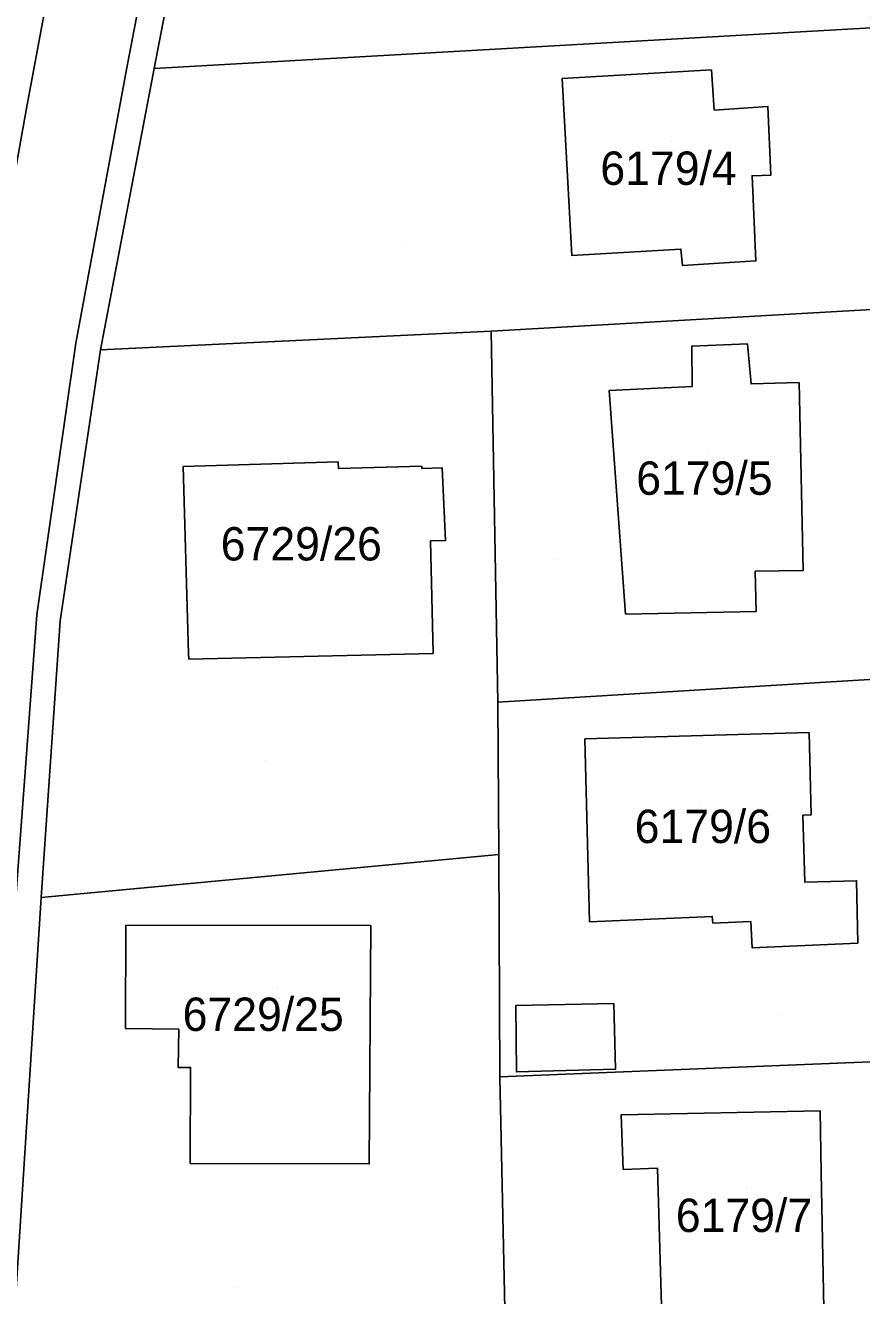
# Model space of a CAD drawing. Extents: x -266199 to -261993, y -1239047 to -1235108.
# Drawn here: x -264003.4 to -263953.2, y -1236187 to -1236110.8 of the extents above; entities that cross this region are included whole.
import ezdxf

# ---------------------------------------------------------------- set-up
doc = ezdxf.new("R2010")
doc.units = 0
for name, color, linetype in [('body_kn', 7, 'Continuous'), ('kladpar_druhypozemkov', 7, 'Continuous'), ('kladpar_hranice', 7, 'Continuous'), ('kladpar_parcelnecisla', 7, 'Continuous'), ('kladpar_plochy', 7, 'Continuous'), ('zappar_hrandruhpozemk', 7, 'Continuous')]:
    doc.layers.add(name, color=color, linetype=linetype)

msp = doc.modelspace()

# ---------------------------------------------------------------- linework, layer by layer
at = {"layer": 'body_kn'}
for p, q in [((-263997.29, -1236113.11), (-263997.29, -1236113.11)), ((-263995.69, -1236113.37), (-263995.69, -1236113.37)), ((-263971.21, -1236113.95), (-263971.21, -1236113.95)), ((-263962.26, -1236113.45), (-263962.26, -1236113.45)), ((-263958.87, -1236115.63), (-263958.87, -1236115.63)), ((-264003.37, -1236115.85), (-264003.37, -1236115.85)), ((-263962.09, -1236115.86), (-263962.09, -1236115.86)), ((-263962.09, -1236115.86), (-263962.09, -1236115.86)), ((-263959.82, -1236119.79), (-263959.82, -1236119.79)), ((-263958.7, -1236119.76), (-263958.7, -1236119.76)), ((-263970.63, -1236124.58), (-263970.63, -1236124.58)), ((-263964.09, -1236124.19), (-263964.09, -1236124.19)), ((-263964, -1236125.18), (-263964, -1236125.18)), ((-263959.59, -1236124.9), (-263959.59, -1236124.9)), ((-263975.47, -1236129.12), (-263975.47, -1236129.12)), ((-264000.38, -1236129.83), (-264000.38, -1236129.83)), ((-263963.44, -1236130.01), (-263963.44, -1236130.01)), ((-263960.1, -1236129.87), (-263960.1, -1236129.87)), ((-263998.9, -1236130.23), (-263998.9, -1236130.23)), ((-263963.42, -1236132.44), (-263963.42, -1236132.44)), ((-263959.88, -1236132.28), (-263959.88, -1236132.28)), ((-263957, -1236132.2), (-263957, -1236132.2)), ((-263957, -1236132.2), (-263957, -1236132.2)), ((-263968.39, -1236132.67), (-263968.39, -1236132.67)), ((-263984.65, -1236136.96), (-263984.65, -1236136.96)), ((-263984.65, -1236136.96), (-263984.65, -1236136.96)), ((-263993.96, -1236137.24), (-263993.96, -1236137.24)), ((-263984.64, -1236137.36), (-263984.64, -1236137.36)), ((-263979.64, -1236137.22), (-263979.64, -1236137.22)), ((-263979.64, -1236137.35), (-263979.64, -1236137.35)), ((-263978.42, -1236137.32), (-263978.42, -1236137.32)), ((-263979.11, -1236141.7), (-263979.11, -1236141.7)), ((-263978.21, -1236141.68), (-263978.21, -1236141.68)), ((-263959.63, -1236143.52), (-263959.63, -1236143.52)), ((-263956.75, -1236143.47), (-263956.75, -1236143.47)), ((-264002.72, -1236146.14), (-264002.72, -1236146.14)), ((-263967.42, -1236146.1), (-263967.42, -1236146.1)), ((-263959.58, -1236145.93), (-263959.58, -1236145.93)), ((-264001.32, -1236146.49), (-264001.32, -1236146.49)), ((-263993.63, -1236148.45), (-263993.63, -1236148.45)), ((-263978.96, -1236148.45), (-263978.96, -1236148.45)), ((-263993.62, -1236148.79), (-263993.62, -1236148.79)), ((-263975.07, -1236151.37), (-263975.07, -1236151.37)), ((-263969.85, -1236153.57), (-263969.85, -1236153.57)), ((-263956.4, -1236153.19), (-263956.4, -1236153.19)), ((-263956.77, -1236158.14), (-263956.77, -1236158.14)), ((-263956.27, -1236158.12), (-263956.27, -1236158.12)), ((-263975.01, -1236160.51), (-263975.01, -1236160.51)), ((-263975.01, -1236160.51), (-263975.01, -1236160.51)), ((-263956.66, -1236162.16), (-263956.66, -1236162.16)), ((-263953.55, -1236162.08), (-263953.55, -1236162.08)), ((-264002.46, -1236163.09), (-264002.46, -1236163.09)), ((-264002.46, -1236163.09), (-264002.46, -1236163.09)), ((-263962.21, -1236164.22), (-263962.21, -1236164.22)), ((-263997.39, -1236164.75), (-263997.39, -1236164.75)), ((-263982.69, -1236164.77), (-263982.69, -1236164.77)), ((-263969.57, -1236164.54), (-263969.57, -1236164.54)), ((-263962.17, -1236164.62), (-263962.17, -1236164.62)), ((-263962.17, -1236164.62), (-263962.17, -1236164.62)), ((-263959.89, -1236164.53), (-263959.89, -1236164.53)), ((-263953.48, -1236165.82), (-263953.48, -1236165.82)), ((-263959.82, -1236166.1), (-263959.82, -1236166.1)), ((-263974, -1236169.56), (-263974, -1236169.56)), ((-263968.12, -1236169.44), (-263968.12, -1236169.44)), ((-263968.12, -1236169.44), (-263968.12, -1236169.44)), ((-263997.4, -1236170.95), (-263997.4, -1236170.95)), ((-263994.22, -1236170.99), (-263994.22, -1236170.99)), ((-263994.26, -1236173.28), (-263994.26, -1236173.28)), ((-263993.52, -1236173.28), (-263993.52, -1236173.28)), ((-263973.96, -1236173.55), (-263973.96, -1236173.55)), ((-263968.02, -1236173.39), (-263968.02, -1236173.39)), ((-263974.95, -1236173.84), (-263974.95, -1236173.84)), ((-263974.95, -1236173.84), (-263974.95, -1236173.84)), ((-263955.74, -1236175.89), (-263955.74, -1236175.89)), ((-263967.67, -1236176.12), (-263967.67, -1236176.12)), ((-263993.53, -1236179.05), (-263993.53, -1236179.05)), ((-263993.53, -1236179.05), (-263993.53, -1236179.05)), ((-263982.79, -1236179.07), (-263982.79, -1236179.07)), ((-263967.55, -1236179.4), (-263967.55, -1236179.4)), ((-263965.5, -1236179.32), (-263965.5, -1236179.32)), ((-263955.67, -1236179.59), (-263955.67, -1236179.59))]:
    msp.add_line(p, q, dxfattribs=at)
at = {"layer": 'kladpar_druhypozemkov'}
for p, q in [((-263964.64, -1236117.74), (-263964.64, -1236117.74)), ((-263980.83, -1236124.05), (-263980.83, -1236124.05)), ((-263962.43, -1236136.33), (-263962.43, -1236136.33)), ((-263986.06, -1236140.27), (-263986.06, -1236140.27)), ((-263971.69, -1236142.84), (-263971.69, -1236142.84)), ((-263989.05, -1236154.86), (-263989.05, -1236154.86)), ((-263962.92, -1236157.49), (-263962.92, -1236157.49)), ((-263988.29, -1236168.49), (-263988.29, -1236168.49)), ((-263958.26, -1236170.12), (-263958.26, -1236170.12)), ((-263971.01, -1236171.49), (-263971.01, -1236171.49)), ((-263960.16, -1236180.55), (-263960.16, -1236180.55)), ((-263990.89, -1236186.48), (-263990.89, -1236186.48))]:
    msp.add_line(p, q, dxfattribs=at)
at = {"layer": 'kladpar_hranice'}
for points in [[(-263968.71, -1236039.76), (-263967.92, -1236051.04), (-263967.62, -1236055.28), (-263972.39, -1236055.85), (-263980.46, -1236061.22), (-263980.53, -1236061.33), (-263983.71, -1236066.05), (-263984.36, -1236067.51), (-263985.67, -1236070.42), (-263988.11, -1236077.51), (-263988.98, -1236080.03), (-263991.79, -1236092.59), (-263992.35, -1236096.02), (-263995.69, -1236113.37), (-263998.9, -1236130.23), (-264001.32, -1236146.49), (-264002.46, -1236163.09), (-264004.38, -1236193.13)], [(-263953.52, -1236093.92), (-263952.67, -1236110.92), (-263995.69, -1236113.37), (-263992.35, -1236096.02), (-263953.52, -1236093.92)], [(-263952.67, -1236110.92), (-263951.91, -1236127.77), (-263975.47, -1236129.12), (-263998.9, -1236130.23), (-263995.69, -1236113.37), (-263952.67, -1236110.92)], [(-263951.91, -1236127.77), (-263951.14, -1236149.91), (-263975.07, -1236151.37), (-263975.47, -1236129.12), (-263951.91, -1236127.77)], [(-264002.46, -1236163.09), (-264001.32, -1236146.49), (-263998.9, -1236130.23), (-263975.47, -1236129.12), (-263975.07, -1236151.37), (-263975.01, -1236160.51), (-264002.46, -1236163.09)], [(-263975.01, -1236160.51), (-263975.07, -1236151.37), (-263951.14, -1236149.91), (-263950.24, -1236172.84), (-263974.95, -1236173.84), (-263975.01, -1236160.51)], [(-264004.38, -1236193.13), (-264002.46, -1236163.09), (-263975.01, -1236160.51), (-263974.95, -1236173.84), (-263974.58, -1236191.46), (-264004.38, -1236193.13)], [(-263974.95, -1236173.84), (-263950.24, -1236172.84), (-263949.46, -1236197.58), (-263974.65, -1236199.08), (-263974.58, -1236191.46), (-263974.95, -1236173.84)]]:
    msp.add_lwpolyline(points, dxfattribs=at)
at = {"layer": 'kladpar_plochy'}
msp.add_lwpolyline([(-263968.71, -1236039.76), (-263967.92, -1236051.04), (-263967.62, -1236055.28), (-263972.39, -1236055.85), (-263980.46, -1236061.22), (-263980.53, -1236061.33), (-263983.71, -1236066.05), (-263984.36, -1236067.51), (-263985.67, -1236070.42), (-263988.11, -1236077.51), (-263988.98, -1236080.03), (-263991.79, -1236092.59), (-263992.35, -1236096.02), (-263995.69, -1236113.37), (-263998.9, -1236130.23), (-264001.32, -1236146.49), (-264002.46, -1236163.09), (-264004.38, -1236193.13)], dxfattribs=at)
for points in [[(-263953.52, -1236093.92), (-263952.67, -1236110.92), (-263995.69, -1236113.37), (-263992.35, -1236096.02)], [(-263952.67, -1236110.92), (-263951.91, -1236127.77), (-263975.47, -1236129.12), (-263998.9, -1236130.23), (-263995.69, -1236113.37)], [(-263951.91, -1236127.77), (-263951.14, -1236149.91), (-263975.07, -1236151.37), (-263975.47, -1236129.12)], [(-264002.46, -1236163.09), (-264001.32, -1236146.49), (-263998.9, -1236130.23), (-263975.47, -1236129.12), (-263975.07, -1236151.37), (-263975.01, -1236160.51)], [(-263975.01, -1236160.51), (-263975.07, -1236151.37), (-263951.14, -1236149.91), (-263950.24, -1236172.84), (-263974.95, -1236173.84)], [(-264004.38, -1236193.13), (-264002.46, -1236163.09), (-263975.01, -1236160.51), (-263974.95, -1236173.84), (-263974.58, -1236191.46)], [(-263974.95, -1236173.84), (-263950.24, -1236172.84), (-263949.46, -1236197.58), (-263974.65, -1236199.08), (-263974.58, -1236191.46)]]:
    msp.add_lwpolyline(points, close=True, dxfattribs=at)
at = {"layer": 'zappar_hrandruhpozemk'}
for p, q in [((-263997.29, -1236113.11), (-264000.38, -1236129.83)), ((-263971.21, -1236113.95), (-263962.26, -1236113.45)), ((-263962.26, -1236113.45), (-263962.09, -1236115.86)), ((-263967.42, -1236146.1), (-263968.39, -1236132.67)), ((-263978.96, -1236148.45), (-263993.62, -1236148.79)), ((-263956.4, -1236153.19), (-263969.85, -1236153.57)), ((-263982.69, -1236164.77), (-263997.39, -1236164.75)), ((-263968.12, -1236169.44), (-263974, -1236169.56)), ((-263955.52, -1236187.74), (-263955.67, -1236179.59))]:
    msp.add_line(p, q, dxfattribs=at)
for points in [[(-263985.01, -1236065.3), (-263986.95, -1236069.79), (-263988.81, -1236075.47), (-263990.23, -1236079.49), (-263993.24, -1236092.2), (-263993.94, -1236095.64), (-263997.29, -1236113.11)], [(-263998.6, -1236090.71), (-263999.85, -1236096.96), (-264003.37, -1236115.85), (-264006.52, -1236133.47), (-264008.73, -1236151.49)], [(-263962.09, -1236115.86), (-263958.87, -1236115.63), (-263958.7, -1236119.76), (-263959.82, -1236119.79), (-263959.59, -1236124.9), (-263964, -1236125.18), (-263964.09, -1236124.19), (-263970.63, -1236124.58), (-263971.21, -1236113.95)], [(-264000.38, -1236129.83), (-264002.72, -1236146.14), (-264003.96, -1236162.83), (-264005.62, -1236192.9)], [(-263968.39, -1236132.67), (-263963.42, -1236132.44), (-263963.44, -1236130.01), (-263960.1, -1236129.87), (-263959.88, -1236132.28), (-263957, -1236132.2)], [(-263957, -1236132.2), (-263956.75, -1236143.47), (-263959.63, -1236143.52), (-263959.58, -1236145.93), (-263967.42, -1236146.1)], [(-263993.62, -1236148.79), (-263993.63, -1236148.45), (-263993.96, -1236137.24), (-263984.65, -1236136.96)], [(-263984.65, -1236136.96), (-263984.64, -1236137.36), (-263979.64, -1236137.22), (-263979.64, -1236137.35), (-263978.42, -1236137.32), (-263978.21, -1236141.68), (-263979.11, -1236141.7), (-263978.96, -1236148.45)], [(-263969.85, -1236153.57), (-263969.57, -1236164.54), (-263962.21, -1236164.22), (-263962.17, -1236164.62)], [(-263962.17, -1236164.62), (-263959.89, -1236164.53), (-263959.82, -1236166.1), (-263953.48, -1236165.82), (-263953.55, -1236162.08), (-263956.66, -1236162.16), (-263956.77, -1236158.14), (-263956.27, -1236158.12), (-263956.4, -1236153.19)], [(-263997.39, -1236164.75), (-263997.4, -1236170.95), (-263994.22, -1236170.99), (-263994.26, -1236173.28), (-263993.52, -1236173.28), (-263993.53, -1236179.05)], [(-263993.53, -1236179.05), (-263982.79, -1236179.07), (-263982.69, -1236164.77)], [(-263974, -1236169.56), (-263973.96, -1236173.55), (-263968.02, -1236173.39), (-263968.12, -1236169.44)], [(-263955.67, -1236179.59), (-263955.74, -1236175.89), (-263967.67, -1236176.12), (-263967.55, -1236179.4), (-263965.5, -1236179.32), (-263965.19, -1236189.64)]]:
    msp.add_lwpolyline(points, dxfattribs=at)

# ---------------------------------------------------------------- texts
at = {"layer": 'kladpar_parcelnecisla'}
for s, p in [('6179/4', (-263968.923, -1236120.34)), ('6179/5', (-263966.768, -1236138.93)), ('6729/26', (-263991.697, -1236142.87)), ('6179/6', (-263966.863, -1236159.82)), ('6729/25', (-263993.982, -1236171.09)), ('6179/7', (-263964.396, -1236183.15))]:
    msp.add_text(s, height=2, dxfattribs=at).set_placement(p)

doc.saveas('drawing.dxf')
